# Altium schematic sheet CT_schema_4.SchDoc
size 411 x 401 mm
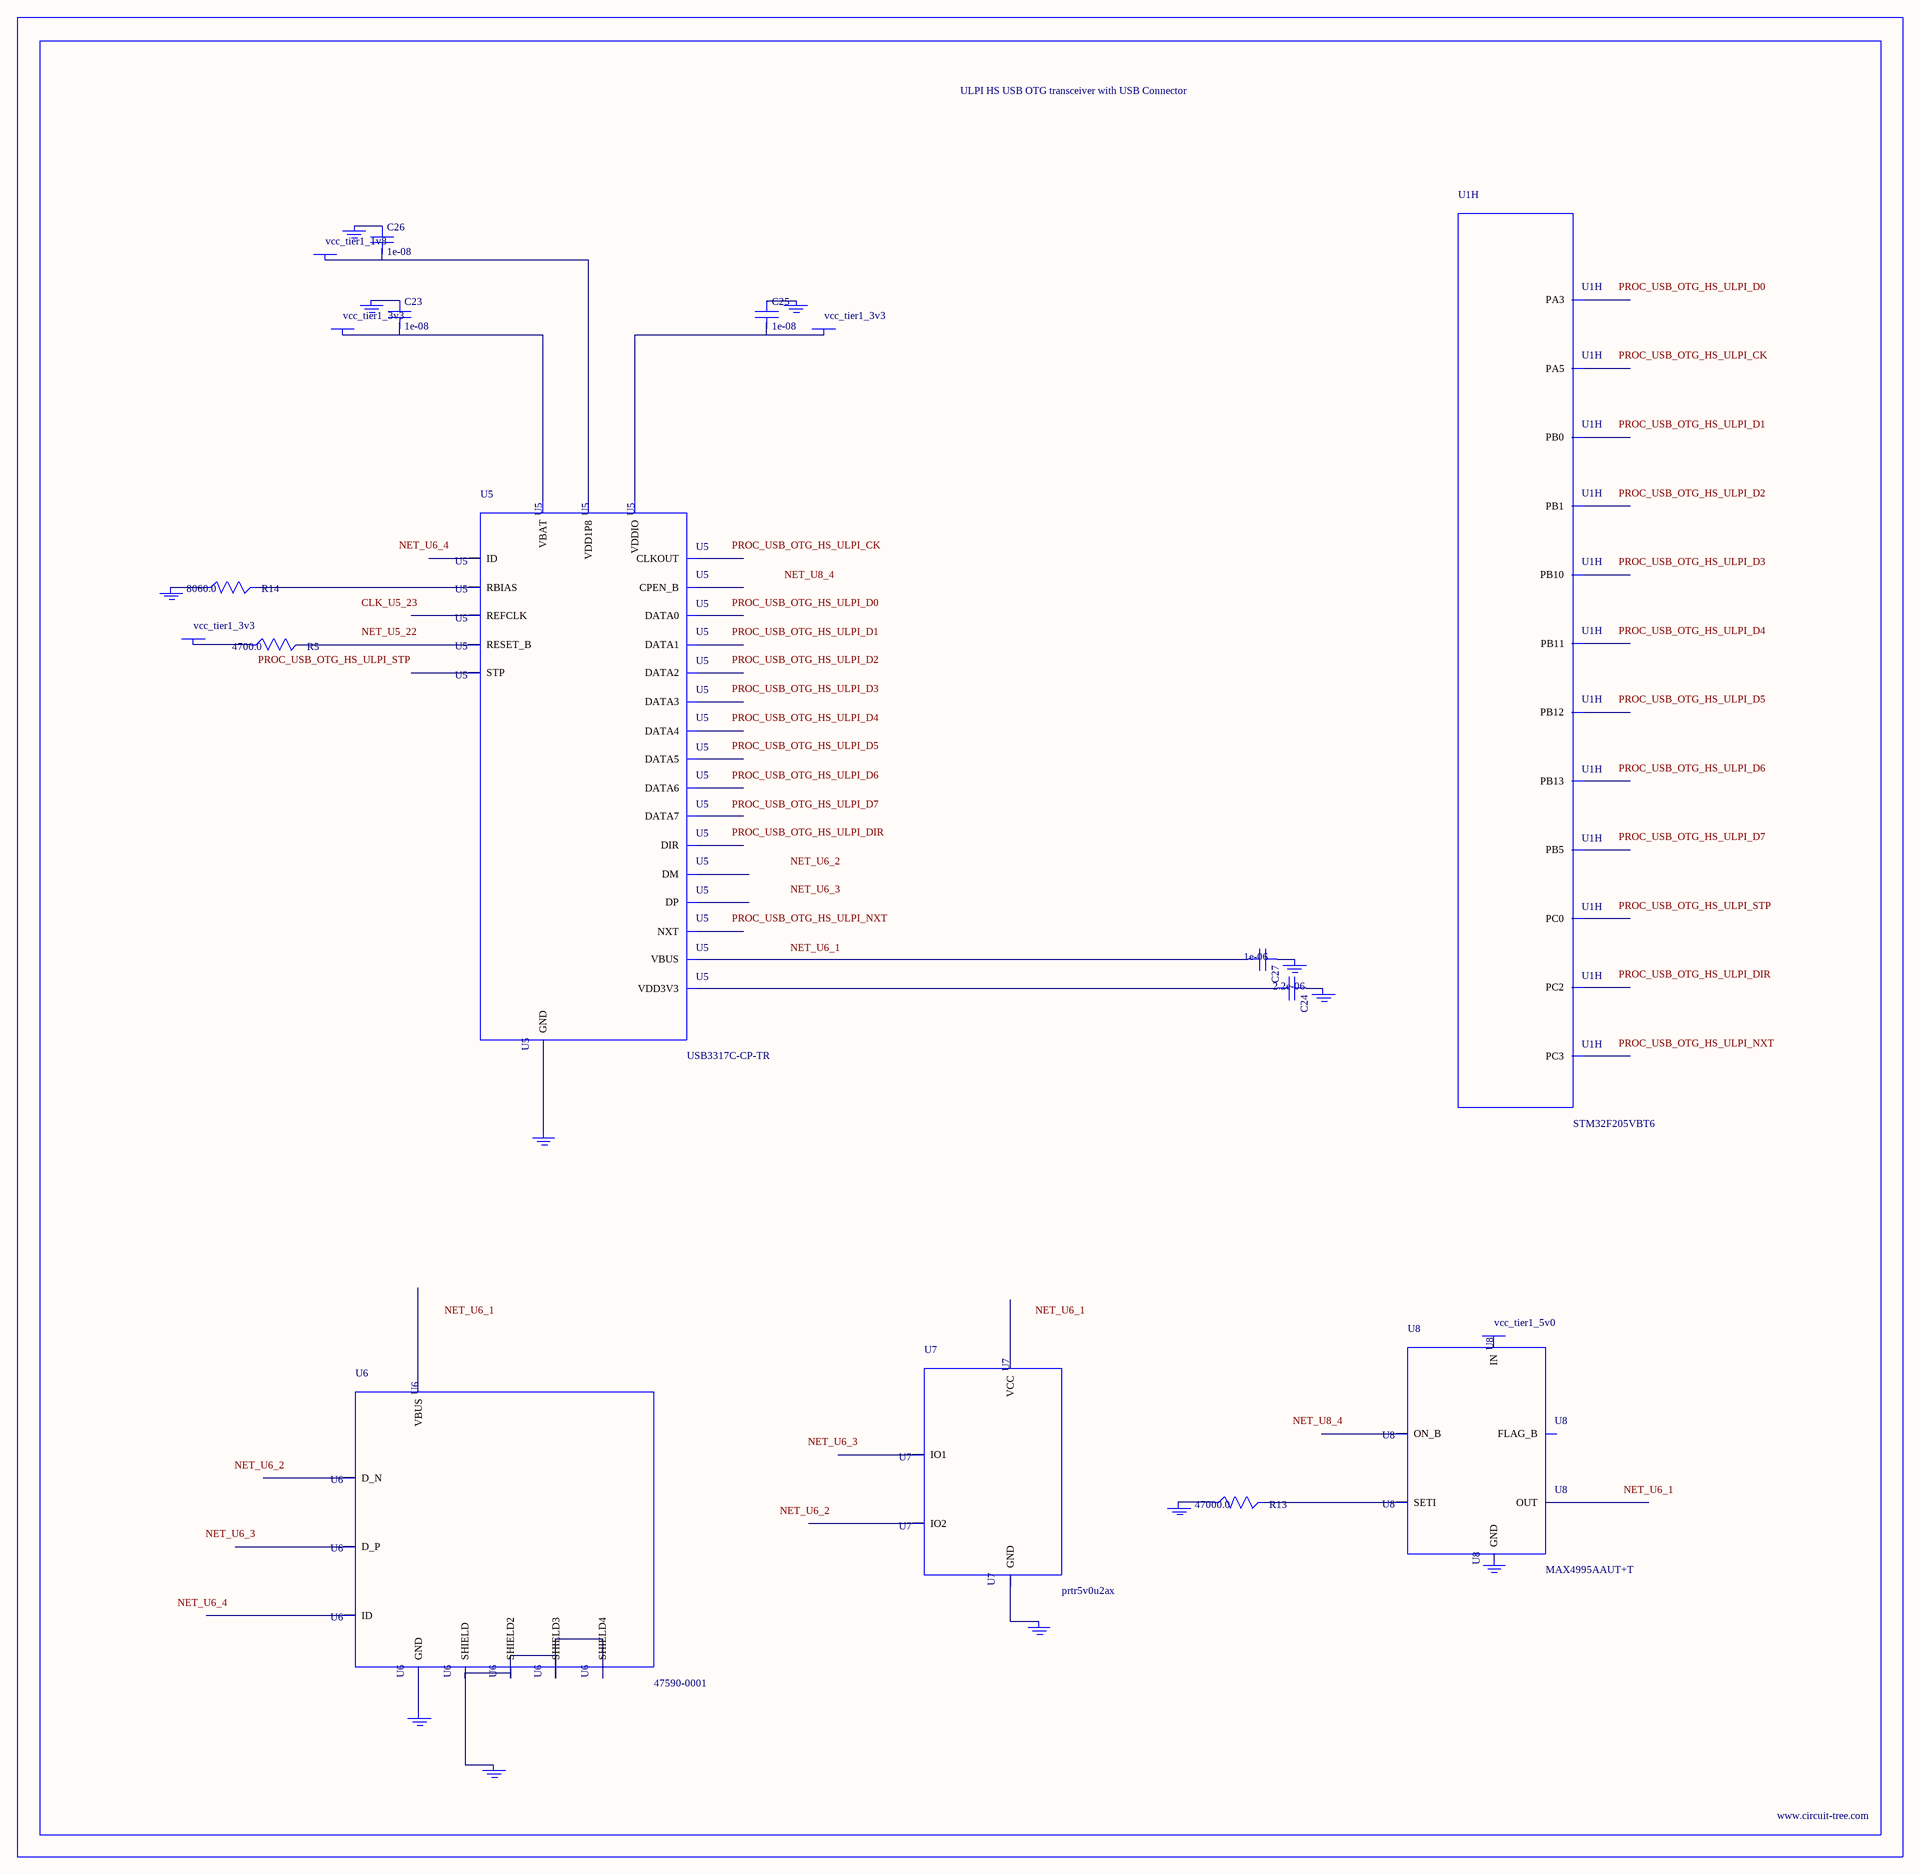
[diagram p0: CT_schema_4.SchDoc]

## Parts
BORDER3  (no value)
C23  1e-08  [C0402]
C24  2.2e-06  [C0603]
C25  1e-08  [C0402]
C26  1e-08  [C0402]
C27  1e-06  [C0603]
GND_INSTANCE_3_0  (no value)
GND_INSTANCE_3_1  (no value)
GND_INSTANCE_3_2  (no value)
GND_INSTANCE_3_3  (no value)
GND_INSTANCE_3_4  (no value)
GND_INSTANCE_3_5  (no value)
GND_INSTANCE_3_6  (no value)
GND_INSTANCE_3_7  (no value)
GND_INSTANCE_3_8  (no value)
GND_INSTANCE_3_9  (no value)
GND_INSTANCE_3_10  (no value)
GND_INSTANCE_3_11  (no value)
POWER_INSTANCE_3_0  vcc_tier1_3v3
POWER_INSTANCE_3_1  vcc_tier1_3v3
POWER_INSTANCE_3_2  vcc_tier1_1v8
POWER_INSTANCE_3_3  vcc_tier1_3v3
POWER_INSTANCE_3_4  vcc_tier1_5v0
R5  4700.0  [R0603]
R13  47000.0  [R0603]
R14  8060.0  [R0603]
U1  STM32F205VBT6  [LQFP100]  (part H of 8)
U5  USB3317C-CP-TR  [QFN-24]
U6  47590-0001  [MICRO_USB_AB]
U7  prtr5v0u2ax  [SOT143B]
U8  MAX4995AAUT+T  [SOT-23-6]

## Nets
NetC23_1: C23.1 GND_INSTANCE_3_1.0(GND)
NetC23_2: C23.2 POWER_INSTANCE_3_0.0(PWR) U5.3(VBAT)
NetC24_1: C24.1 GND_INSTANCE_3_2.0(GND)
NetC24_2: C24.2 U5.4(VDD3V3)
NetC25_1: C25.1 GND_INSTANCE_3_3.0(GND)
NetC25_2: C25.2 POWER_INSTANCE_3_1.0(PWR) U5.17(VDDIO)
NetC26_1: C26.1 GND_INSTANCE_3_4.0(GND)
NetC26_2: C26.2 POWER_INSTANCE_3_2.0(PWR) U5.21(VDD1P8)
NetC27_1: C27.1 GND_INSTANCE_3_0.0(GND)
NetC27_2: C27.2 U5.2(VBUS)
NetGND_INSTANCE_3_5_0: GND_INSTANCE_3_5.0(GND) R14.1
NetGND_INSTANCE_3_6_0: GND_INSTANCE_3_6.0(GND) U5.25(GND)
NetGND_INSTANCE_3_7_0: GND_INSTANCE_3_7.0(GND) U6.6(SHIELD) U6.7(SHIELD2) U6.8(SHIELD3) U6.9(SHIELD4)
NetGND_INSTANCE_3_8_0: GND_INSTANCE_3_8.0(GND) U6.5(GND)
NetGND_INSTANCE_3_9_0: GND_INSTANCE_3_9.0(GND) U7.1(GND)
NetGND_INSTANCE_3_10_0: GND_INSTANCE_3_10.0(GND) R13.1
NetPOWER_INSTANCE_3_3_0: POWER_INSTANCE_3_3.0(PWR) R5.1
NetR5_2: R5.2 U5.22(RESET_B)
NetR13_2: R13.2 U8.3(SETI)
NetR14_2: R14.2 U5.24(RBIAS)

Not connected (* = marked no-connect by the designer): GND_INSTANCE_3_11 0(GND); POWER_INSTANCE_3_4 0(PWR); U1 15(PC0) 17(PC2) 18(PC3) 26(PA3) 30(PA5) 35(PB0) 36(PB1) 47(PB10) 48(PB11) 51(PB12) 52(PB13) 91(PB5); U5 1(ID) 5(DM) 6(DP) 7(CPEN_B) 8(DATA7) 9(DATA6) 10(DATA5) 11(DATA4) 12(CLKOUT) 13(DATA3) 14(DATA2) 15(DATA1) 16(DATA0) 18(NXT) 19(DIR) 20(STP) 23(REFCLK); U6 1(VBUS) 2(D_N) 3(D_P) 4(ID); U7 2(IO1) 3(IO2) 4(VCC); U8 1(OUT) 2(GND) 4(ON_B) 5(IN) 6(FLAG_B)

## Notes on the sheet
- Labels drawn without touching a wire or pin: CLK_U5_23, NET_U5_22, NET_U6_1, NET_U6_2, NET_U6_3, NET_U6_4, NET_U8_4, PROC_USB_OTG_HS_ULPI_CK, PROC_USB_OTG_HS_ULPI_D0, PROC_USB_OTG_HS_ULPI_D1, PROC_USB_OTG_HS_ULPI_D2, PROC_USB_OTG_HS_ULPI_D3, PROC_USB_OTG_HS_ULPI_D4, PROC_USB_OTG_HS_ULPI_D5, PROC_USB_OTG_HS_ULPI_D6, PROC_USB_OTG_HS_ULPI_D7, PROC_USB_OTG_HS_ULPI_DIR, PROC_USB_OTG_HS_ULPI_NXT, PROC_USB_OTG_HS_ULPI_STP

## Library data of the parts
BORDER3 = BORDER_PAGE3
C23 C25 C26 = C0402C103K3RAC
C24 = C0603C225K8RACTU
C27 = C0603C105K3RACTU
GND_INSTANCE_3_0-GND_INSTANCE_3_11 = GND
POWER_INSTANCE_3_0-POWER_INSTANCE_3_4 = PWR
R5 = RC0603JR-074K7L
R13 = RC0603JR-0747KL
R14 = ERJ-3EKF8061V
